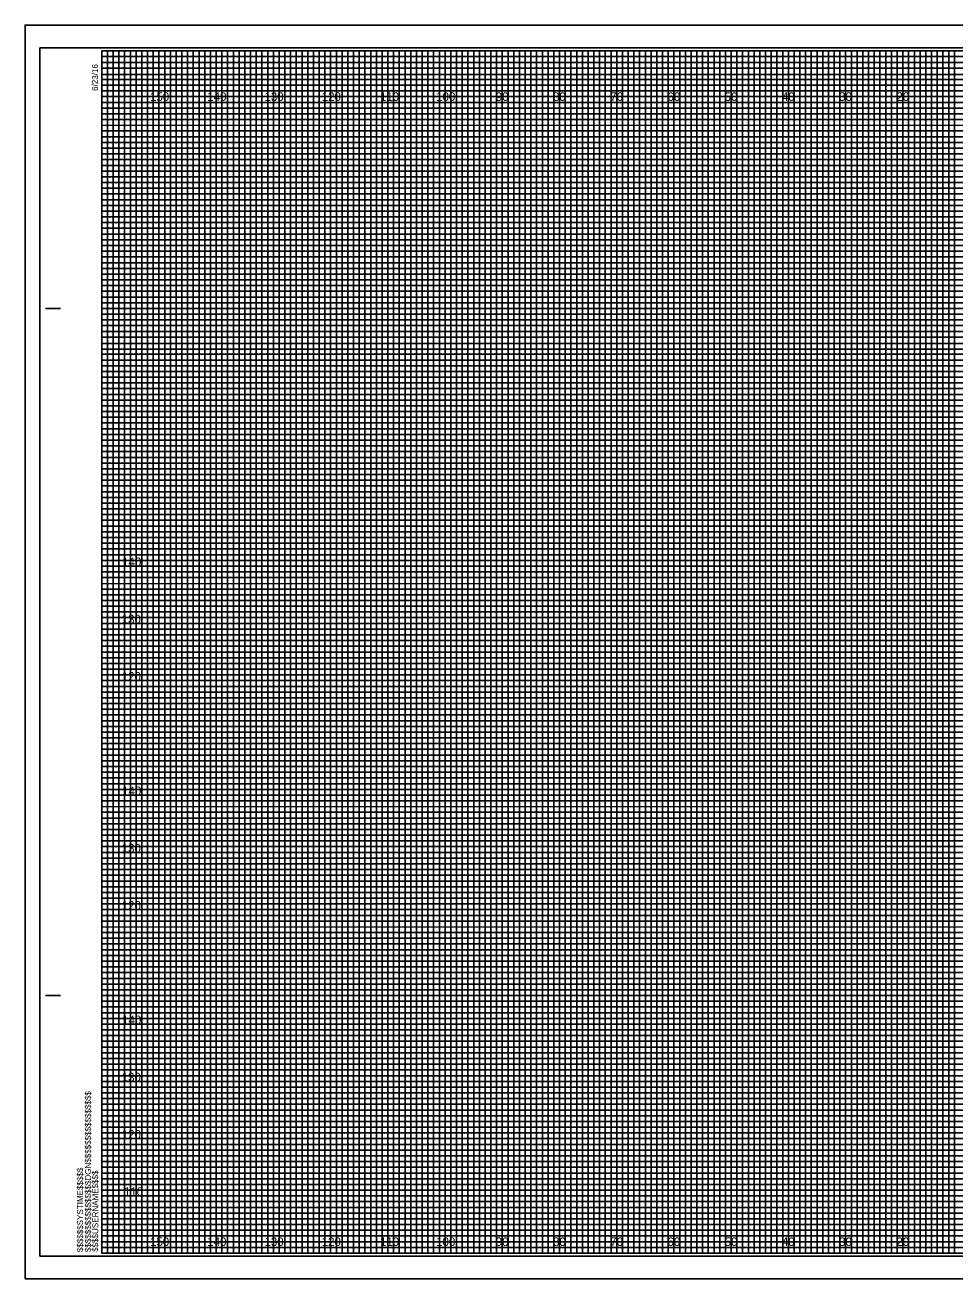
# Model space of a CAD drawing. Extents: x -13 to 323, y -5 to 654.
# Drawn here: x -13.4 to 149.1, y 435.5 to 654.5 of the extents above; entities that cross this region are included whole.
import ezdxf

# ---------------------------------------------------------------- set-up
doc = ezdxf.new("R2010")
doc.units = 0
for name, color, linetype in [('Prop XS Elevation Labels', 7, 'Continuous'), ('Prop XS Offset Labels', 7, 'Continuous'), ('Sheet Cross Section CELL', 7, 'Continuous'), ('Sheet Cross Section Grid Major CELL', 7, 'Continuous'), ('Sheet Cross Section Grid Middle CELL', 7, 'Continuous'), ('Sheet Cross Section Grid Minor 1 CELL', 7, 'Continuous'), ('Sheet Cross Section Grid Minor 2 CELL', 7, 'Continuous'), ('Sheet Cutting Line CELL', 7, 'Continuous'), ('Sheet DOT Grid CELL', 7, 'Continuous'), ('Sheet Plot Border Inside CELL', 7, 'Continuous'), ('Sheet Plot Border Outside CELL', 7, 'Continuous')]:
    doc.layers.add(name, color=color, linetype=linetype)

msp = doc.modelspace()

# ---------------------------------------------------------------- linework, layer by layer
at = {"layer": 'Sheet Cross Section CELL'}
for p, q in [((-9.8, 605), (-7.3, 605)), ((-9.7, 605), (-7.2, 605)), ((-9.8, 485), (-7.3, 485)), ((-9.7, 485), (-7.2, 485)), ((0, 440), (0, 440)), ((0, 440), (0, 440)), ((0, 440), (0, 440)), ((0, 440), (0, 440)), ((0, 440), (0, 440)), ((0, 440), (0, 440)), ((0, 440), (0, 440))]:
    msp.add_line(p, q, dxfattribs=at)
msp.add_lwpolyline([(320, 650), (0, 650), (0, 440), (320, 440)], close=True, dxfattribs=at)
at = {"layer": 'Sheet Cross Section Grid Major CELL'}
for p, q in [((10, 650), (0, 650)), ((10, 440), (10, 650)), ((30, 650), (20, 650)), ((20, 650), (20, 440)), ((30, 440), (30, 650)), ((50, 650), (40, 650)), ((40, 650), (40, 440)), ((50, 440), (50, 650)), ((70, 650), (60, 650)), ((60, 650), (60, 440)), ((70, 440), (70, 650)), ((90, 650), (80, 650)), ((80, 650), (80, 440)), ((90, 440), (90, 650)), ((110, 650), (100, 650)), ((100, 650), (100, 440)), ((110, 440), (110, 650)), ((130, 650), (120, 650)), ((120, 650), (120, 440)), ((130, 440), (130, 650)), ((150, 650), (140, 650)), ((140, 650), (140, 440)), ((20, 440), (10, 440)), ((40, 440), (30, 440)), ((60, 440), (50, 440)), ((80, 440), (70, 440)), ((100, 440), (90, 440)), ((120, 440), (110, 440)), ((140, 440), (130, 440))]:
    msp.add_line(p, q, dxfattribs=at)
for points in [[(0, 640), (320, 640), (320, 630), (0, 630)], [(0, 620), (320, 620), (320, 610), (0, 610)], [(0, 600), (320, 600), (320, 590), (0, 590)], [(0, 580), (320, 580), (320, 570), (0, 570)], [(0, 560), (320, 560), (320, 550), (0, 550)], [(0, 540), (320, 540), (320, 530), (0, 530)], [(0, 520), (320, 520), (320, 510), (0, 510)], [(0, 500), (320, 500), (320, 490), (0, 490)], [(0, 480), (320, 480), (320, 470), (0, 470)], [(0, 460), (320, 460), (320, 450), (0, 450)]]:
    msp.add_lwpolyline(points, dxfattribs=at)
at = {"layer": 'Sheet Cross Section Grid Middle CELL'}
for points in [[(0, 650), (5, 650), (5, 440), (15, 440), (15, 650), (25, 650), (25, 440), (35, 440), (35, 650), (45, 650), (45, 440), (55, 440), (55, 650), (65, 650), (65, 440), (75, 440), (75, 650), (85, 650), (85, 440), (95, 440), (95, 650), (105, 650), (105, 440), (115, 440), (115, 650), (125, 650), (125, 440), (135, 440), (135, 650), (145, 650), (145, 440), (155, 440)], [(0, 645), (275, 645)], [(0, 625), (320, 625), (320, 635), (0, 635)], [(0, 605), (320, 605), (320, 615), (0, 615)], [(0, 585), (320, 585), (320, 595), (0, 595)], [(0, 565), (320, 565), (320, 575), (0, 575)], [(0, 545), (320, 545), (320, 555), (0, 555)], [(0, 525), (320, 525), (320, 535), (0, 535)], [(0, 505), (320, 505), (320, 515), (0, 515)], [(0, 485), (320, 485), (320, 495), (0, 495)], [(0, 465), (320, 465), (320, 475), (0, 475)], [(0, 445), (320, 445), (320, 455), (0, 455)]]:
    msp.add_lwpolyline(points, dxfattribs=at)
at = {"layer": 'Sheet Cross Section Grid Minor 1 CELL'}
for p, q in [((0, 649), (260, 649)), ((260, 647.98), (0, 647.98)), ((0, 647.98), (0, 647)), ((0, 647), (260, 647)), ((260, 645.89), (0, 645.89)), ((0, 645.89), (0, 644)), ((0, 644), (320, 644))]:
    msp.add_line(p, q, dxfattribs=at)
for points in [[(0, 643), (270, 643), (320, 643), (320, 642), (0, 642)], [(0, 641), (320, 641), (320, 639), (0, 639)], [(0, 638), (320, 638), (320, 637), (0, 636.98)], [(0, 636), (320, 636), (320, 634), (0, 634)], [(0, 633), (320, 633), (320, 632), (0, 632)], [(0, 631), (320, 631), (320, 629), (0, 629)], [(0, 628), (320, 628), (320, 627), (0, 627)], [(0, 626), (320, 626), (320, 624), (0, 624)], [(0, 623), (320, 623), (320, 622), (0, 622)], [(0, 621), (320, 621), (320, 619), (0, 619)], [(0, 618), (320, 618), (320, 617), (0, 617)], [(0, 616), (320, 616), (320, 613.95), (320, 613), (320, 612), (0, 612)], [(0, 614), (320, 614), (320, 613), (0, 613)], [(0, 611), (320, 611), (320, 609), (0, 609.03)], [(0, 609.03), (320, 609), (320, 608), (0, 608)], [(0, 607), (320, 607), (320, 606), (0, 606)], [(0, 604), (320, 604), (320, 603), (0, 603)], [(0, 602), (320, 602), (320, 601), (0, 601)], [(-0.07, 598.89), (320, 598.89), (320, 597.88), (-0.07, 597.88)], [(0, 597), (320, 597), (320, 596), (0, 596)], [(0, 594), (320, 594), (320, 593), (0, 593)], [(0, 592), (320, 592), (320, 591), (0, 591)], [(0, 589), (320, 589), (320, 588), (0, 588)], [(0, 587), (320, 587), (320, 586), (0, 586)], [(0, 584), (320, 584), (320, 583), (0, 583)], [(0, 582), (320, 582), (320, 581), (0, 581)], [(0, 579), (320, 579), (319.99, 577.98), (0, 578)], [(0, 577), (320, 577), (320, 576), (0, 576)], [(0, 574), (320, 574), (320, 573), (0, 573)], [(0, 572), (320, 572), (320, 571), (0, 571)], [(0, 569), (320, 569), (320, 568), (0, 568)], [(0, 567), (320, 567), (320, 566), (0, 566)], [(0, 564), (320, 564), (320, 563), (0, 563)], [(0, 562), (320, 562), (320, 561), (0, 561)], [(0, 559), (320, 559), (320, 558), (0, 558)], [(0, 556.99), (320.07, 556.91), (320, 556), (0, 556)], [(0, 554), (320, 554), (320, 553), (0, 553)], [(0, 552), (320, 552), (320, 551), (0, 551)], [(0, 549), (320, 549), (320, 548), (0, 548)], [(0, 547), (320, 547), (320, 546), (0, 546)], [(0, 544), (320, 544), (320, 543), (0, 543)], [(0, 542), (320, 542), (320, 541), (0, 541)], [(0, 539), (320, 539), (320, 538), (0, 538)], [(0, 537), (320, 537), (320, 536), (0, 536)], [(0, 534), (320, 534), (320, 533), (0, 533)], [(0, 532), (320, 532), (320, 531), (0, 531)], [(0, 529), (320, 529), (320, 528), (0, 528)], [(0, 527), (320, 527), (320, 526), (0, 526)], [(0, 524), (320, 524), (320, 523), (0, 523)], [(0, 522), (320, 522), (320, 521), (0, 521)], [(0, 519), (320, 519), (319.99, 517.98), (0, 518)], [(0, 517), (320, 517), (320, 516), (0, 516)], [(0, 514), (320, 514), (320, 513), (0, 513)], [(0, 512), (320, 512), (320, 511), (0, 511)], [(0, 509), (320, 509), (320, 508), (0, 508)], [(0, 507), (320, 507), (320, 506), (0, 506)], [(0, 504), (320, 504), (320, 503), (0, 503)], [(0, 502), (320, 502), (320, 501), (0, 501)], [(0, 499), (320, 499), (320, 498), (0, 498)], [(0, 496.99), (320.07, 496.91), (320, 496), (0, 496)], [(0, 494), (320, 494), (320, 493), (0, 493)], [(0, 492), (320, 492), (320, 491), (0, 491)], [(0, 489), (320, 489), (320, 488), (0, 488)], [(0, 487), (320, 487), (320, 486), (0, 486)], [(0, 484), (320, 484), (320, 483), (0, 483)], [(0, 482), (320, 482), (320, 481), (0, 481)], [(0, 479), (320, 479), (320, 478), (0, 478)], [(0, 477), (320, 477), (320, 476), (0, 476)], [(0, 474), (320, 474), (320, 473), (0, 473)], [(0, 472), (320, 472), (320, 471), (0, 471)], [(0, 469), (320, 469), (320, 468), (0, 468)], [(0, 467), (320, 467), (320, 466), (0, 466)], [(0, 464), (320, 464), (320, 463), (0, 463)], [(0, 462), (320, 462), (320, 461), (0, 461)], [(0, 459), (320, 459), (320, 458), (0, 458)], [(0, 457), (320, 457), (320, 456), (0, 456)], [(0, 454), (320, 454), (320, 453), (0, 453)], [(0, 452), (320, 452), (320, 451), (0, 451)], [(0, 449), (320, 449), (320, 448), (0, 448)], [(0, 447), (320, 447), (320, 446), (0, 446)], [(0, 444), (320, 444), (320, 443), (0, 443)], [(0, 442), (320, 442), (320, 441), (0, 441)]]:
    msp.add_lwpolyline(points, dxfattribs=at)
at = {"layer": 'Sheet Cross Section Grid Minor 2 CELL'}
for points in [[(0, 440), (1, 440), (1, 650), (2, 650), (2, 440)], [(2, 440), (3, 440), (3, 650), (4, 650), (4, 440)], [(5, 440), (6, 440), (6, 650), (7, 650), (7, 440)], [(7, 440), (8, 440), (8, 650), (9, 650), (9, 440)], [(10, 440), (11, 440), (11, 650), (12, 650), (12, 440)], [(12, 440), (13, 440), (13, 650), (14, 650), (14, 440)], [(15, 440), (16, 440), (16, 650), (17, 650), (17, 440)], [(17, 440), (18, 440), (18, 650), (19, 650), (19, 440)], [(20, 440), (21, 440), (21, 650), (22, 650), (22, 440)], [(22, 440), (23, 440), (23, 650), (24, 650), (24, 440)], [(25, 440), (26, 440), (26, 650), (27, 650), (27, 440)], [(27, 440), (28, 440), (28, 650), (29, 650), (29, 440)], [(30, 440), (31, 440), (31, 650), (32, 650), (32, 440)], [(32, 440), (33, 440), (33, 650), (34, 650), (34, 440)], [(35, 440), (36, 440), (36, 650), (37, 650), (37, 440)], [(37, 440), (38, 440), (38, 650), (39, 650), (39, 440)], [(40, 440), (41, 440), (41, 650), (42, 650), (42, 440)], [(42, 440), (43, 440), (43, 650), (44, 650), (44, 440)], [(45, 440), (46, 440), (46, 650), (47, 650), (47, 440)], [(47, 440), (48, 440), (48, 650), (49, 650), (49, 440)], [(50, 440), (51, 440), (51, 650), (52, 650), (52, 440)], [(52, 440), (53, 440), (53, 650), (54, 650), (54, 440)], [(55, 440), (56, 440), (56, 650), (57, 650), (57, 440)], [(57, 440), (58, 440), (58, 650), (59, 650), (59, 440)], [(60, 440), (61, 440), (61, 650), (62, 650), (62, 440)], [(62, 440), (63, 440), (63, 650), (64, 650), (64, 440)], [(65, 440), (66, 440), (66, 650), (67, 650), (67, 440)], [(67, 440), (68, 440), (68, 650), (69, 650), (69, 440)], [(70, 440), (71, 440), (71, 650), (72, 650), (72, 440)], [(72, 440), (73, 440), (73, 650), (74, 650), (74, 440)], [(75, 440), (76, 440), (76, 650), (77, 650), (77, 440)], [(77, 440), (78, 440), (78, 650), (79, 650), (79, 440)], [(80, 440), (81, 440), (81, 650), (82, 650), (82, 440)], [(82, 440), (83, 440), (83, 650), (84, 650), (84, 440)], [(85, 440), (86, 440), (86, 650), (87, 650), (87, 440)], [(87, 440), (88, 440), (88, 650), (89, 650), (89, 440)], [(90, 440), (91, 440), (91, 650), (92, 650), (92, 440)], [(92, 440), (93, 440), (93, 650), (94, 650), (94, 440)], [(95, 440), (96, 440), (96, 650), (97, 650), (97, 440)], [(97, 440), (98, 440), (98, 650), (99, 650), (99, 440)], [(100, 440), (101, 440), (101, 650), (102, 650), (102, 440)], [(102, 440), (103, 440), (103, 650), (104, 650), (104, 440)], [(105, 440), (106, 440), (106, 650), (107, 650), (107, 440)], [(107, 440), (108, 440), (108, 650), (109, 650), (109, 440)], [(110, 440), (111, 440), (111, 650), (112, 650), (112, 440)], [(112, 440), (113, 440), (113, 650), (114, 650), (114, 440)], [(115, 440), (116, 440), (116, 650), (117, 650), (117, 440)], [(117, 440), (118, 440), (118, 650), (119, 650), (119, 440)], [(120, 440), (121, 440), (121, 650), (122, 650), (122, 440)], [(122, 440), (123, 440), (123, 650), (124, 650), (124, 440)], [(125, 440), (126, 440), (126, 650), (127, 650), (127, 440)], [(127, 440), (128, 440), (128, 650), (129, 650), (129, 440)], [(130, 440), (131, 440), (131, 650), (132, 650), (132, 440)], [(132, 440), (133, 440), (133, 650), (134, 650), (134, 440)], [(135, 440), (136, 440), (136, 650), (137, 650), (137, 440)], [(137, 440), (138, 440), (138, 650), (139, 650), (139, 440)], [(140, 440), (141, 440), (141, 650), (142, 650), (142, 440)], [(142, 440), (143, 440), (143, 650), (144, 650), (144, 440)], [(145, 440), (146, 440), (146, 650), (147, 650), (147, 440)], [(147, 440), (148, 440), (148, 650), (149, 650), (149, 440)]]:
    msp.add_lwpolyline(points, dxfattribs=at)
at = {"layer": 'Sheet Cutting Line CELL'}
for p, q in [((323.3, 654.5), (-13.4, 654.5)), ((-13.4, 654.5), (-13.4, 435.5)), ((-13.4, 435.5), (323.3, 435.5))]:
    msp.add_line(p, q, dxfattribs=at)
at = {"layer": 'Sheet DOT Grid CELL'}
for p, q in [((10, 440), (10, 650)), ((20, 440), (20, 650)), ((30, 440), (30, 650)), ((40, 440), (40, 650)), ((50, 440), (50, 650)), ((60, 440), (60, 650)), ((70, 440), (70, 650)), ((80, 440), (80, 650)), ((90, 440), (90, 650)), ((100, 440), (100, 650)), ((110, 440), (110, 650)), ((120, 440), (120, 650)), ((130, 440), (130, 650)), ((140, 440), (140, 650)), ((0, 640), (320, 640)), ((0, 630), (320, 630)), ((0, 620), (320, 620)), ((0, 610), (320, 610)), ((0, 600), (320, 600)), ((0, 590), (320, 590)), ((0, 580), (320, 580)), ((0, 570), (320, 570)), ((0, 560), (320, 560)), ((0, 550), (320, 550)), ((0, 540), (320, 540)), ((0, 530), (320, 530)), ((0, 520), (320, 520)), ((0, 510), (320, 510)), ((0, 500), (320, 500)), ((0, 490), (320, 490)), ((0, 480), (320, 480)), ((0, 470), (320, 470)), ((0, 460), (320, 460)), ((0, 450), (320, 450))]:
    msp.add_line(p, q, dxfattribs=at)
at = {"layer": 'Sheet Plot Border Inside CELL'}
msp.add_lwpolyline([(-10.8, 439.5), (322.4, 439.5), (322.4, 650.5), (-10.8, 650.5)], close=True, dxfattribs=at)
at = {"layer": 'Sheet Plot Border Outside CELL'}
msp.add_lwpolyline([(-13.4, 435.5), (323.3, 435.5), (323.3, 654.5), (-13.4, 654.5)], close=True, dxfattribs=at)

# ---------------------------------------------------------------- texts
at = {"layer": 'Prop XS Elevation Labels'}
for s, p in [('140', (3.57, 560)), ('130', (3.49, 550)), ('120', (3.5, 540)), ('140', (3.57, 520)), ('130', (3.49, 510)), ('120', (3.5, 500)), ('140', (3.57, 480)), ('130', (3.49, 470)), ('120', (3.5, 460)), ('110', (3.88, 450))]:
    msp.add_text(s, height=1.5, dxfattribs=at).set_placement(p)
at = {"layer": 'Prop XS Offset Labels'}
for s, p in [('150', (8.44, 641.25)), ('140', (18.44, 641.25)), ('130', (28.44, 641.25)), ('120', (38.44, 641.25)), ('110', (48.62, 641.25)), ('100', (58.44, 641.25)), ('90', (68.86, 641.25)), ('80', (78.86, 641.25)), ('70', (88.86, 641.25)), ('60', (98.86, 641.25)), ('50', (108.86, 641.25)), ('40', (118.86, 641.25)), ('30', (128.86, 641.25)), ('20', (138.86, 641.25)), ('150', (8.44, 441.25)), ('140', (18.44, 441.25)), ('130', (28.44, 441.25)), ('120', (38.44, 441.25)), ('110', (48.62, 441.25)), ('100', (58.44, 441.25)), ('90', (68.86, 441.25)), ('80', (78.86, 441.25)), ('70', (88.86, 441.25)), ('60', (98.86, 441.25)), ('50', (108.86, 441.25)), ('40', (118.86, 441.25)), ('30', (128.86, 441.25)), ('20', (138.86, 441.25))]:
    msp.add_text(s, height=1.5, dxfattribs=at).set_placement(p)
at = {"layer": 'Sheet Cross Section CELL'}
for s, p in [('6/23/16', (-0.65, 643)), ('$$$$$$$$$$$$$$$$DGN$$$$$$$$$$$$$$$$', (-1.88, 440.18)), ('$$$$$$SYSTIME$$$$$', (-3.26, 440.18)), ('$$$$USERNAME$$$$', (-0.62, 440.23))]:
    msp.add_text(s, height=1.05, rotation=90, dxfattribs=at).set_placement(p)

doc.saveas('drawing.dxf')
